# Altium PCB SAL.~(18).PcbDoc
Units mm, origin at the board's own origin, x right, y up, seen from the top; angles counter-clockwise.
Board outline 62 x 78 mm, 2 copper layers (Top Layer, Bottom Layer); 55 components, 64 nets, 231 pads, 15 vias.
Unrouted connection lines stored in the file: 1.
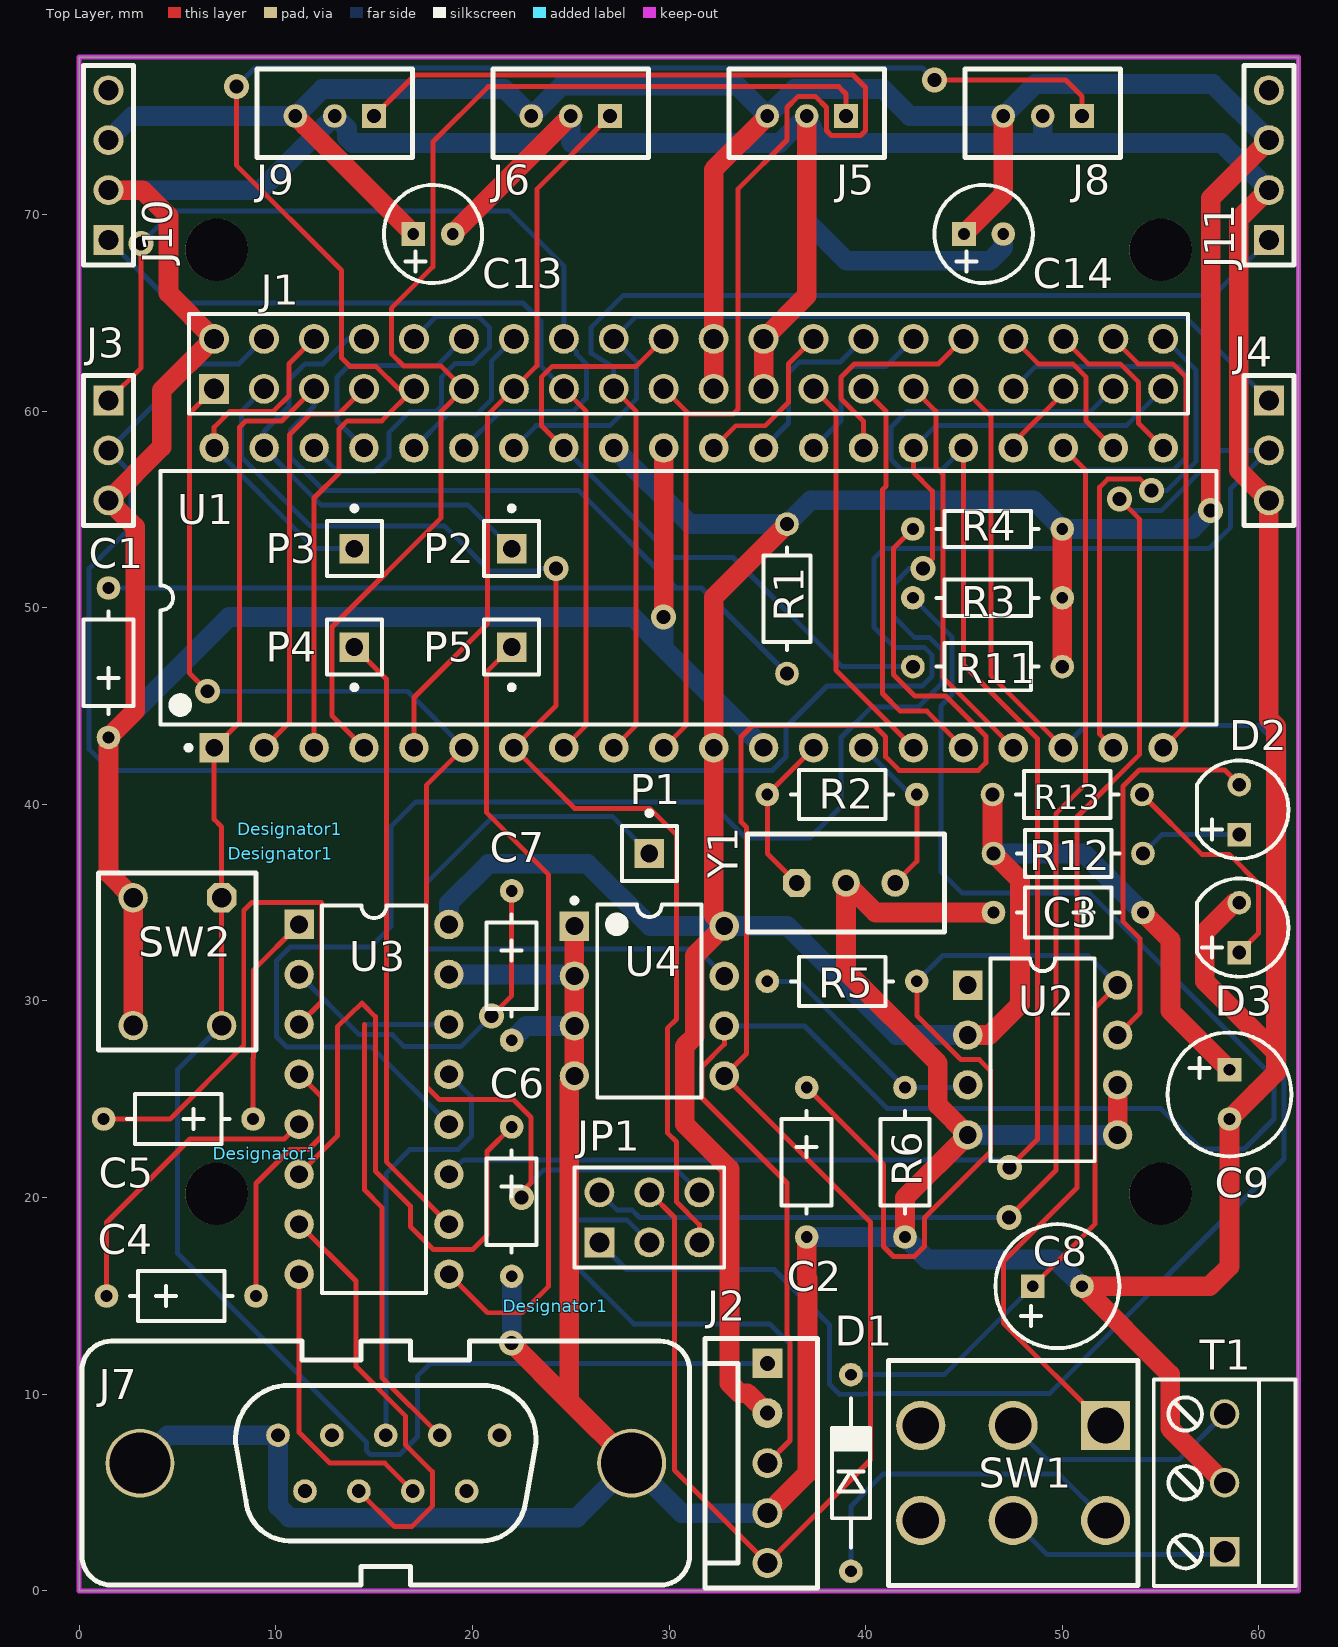
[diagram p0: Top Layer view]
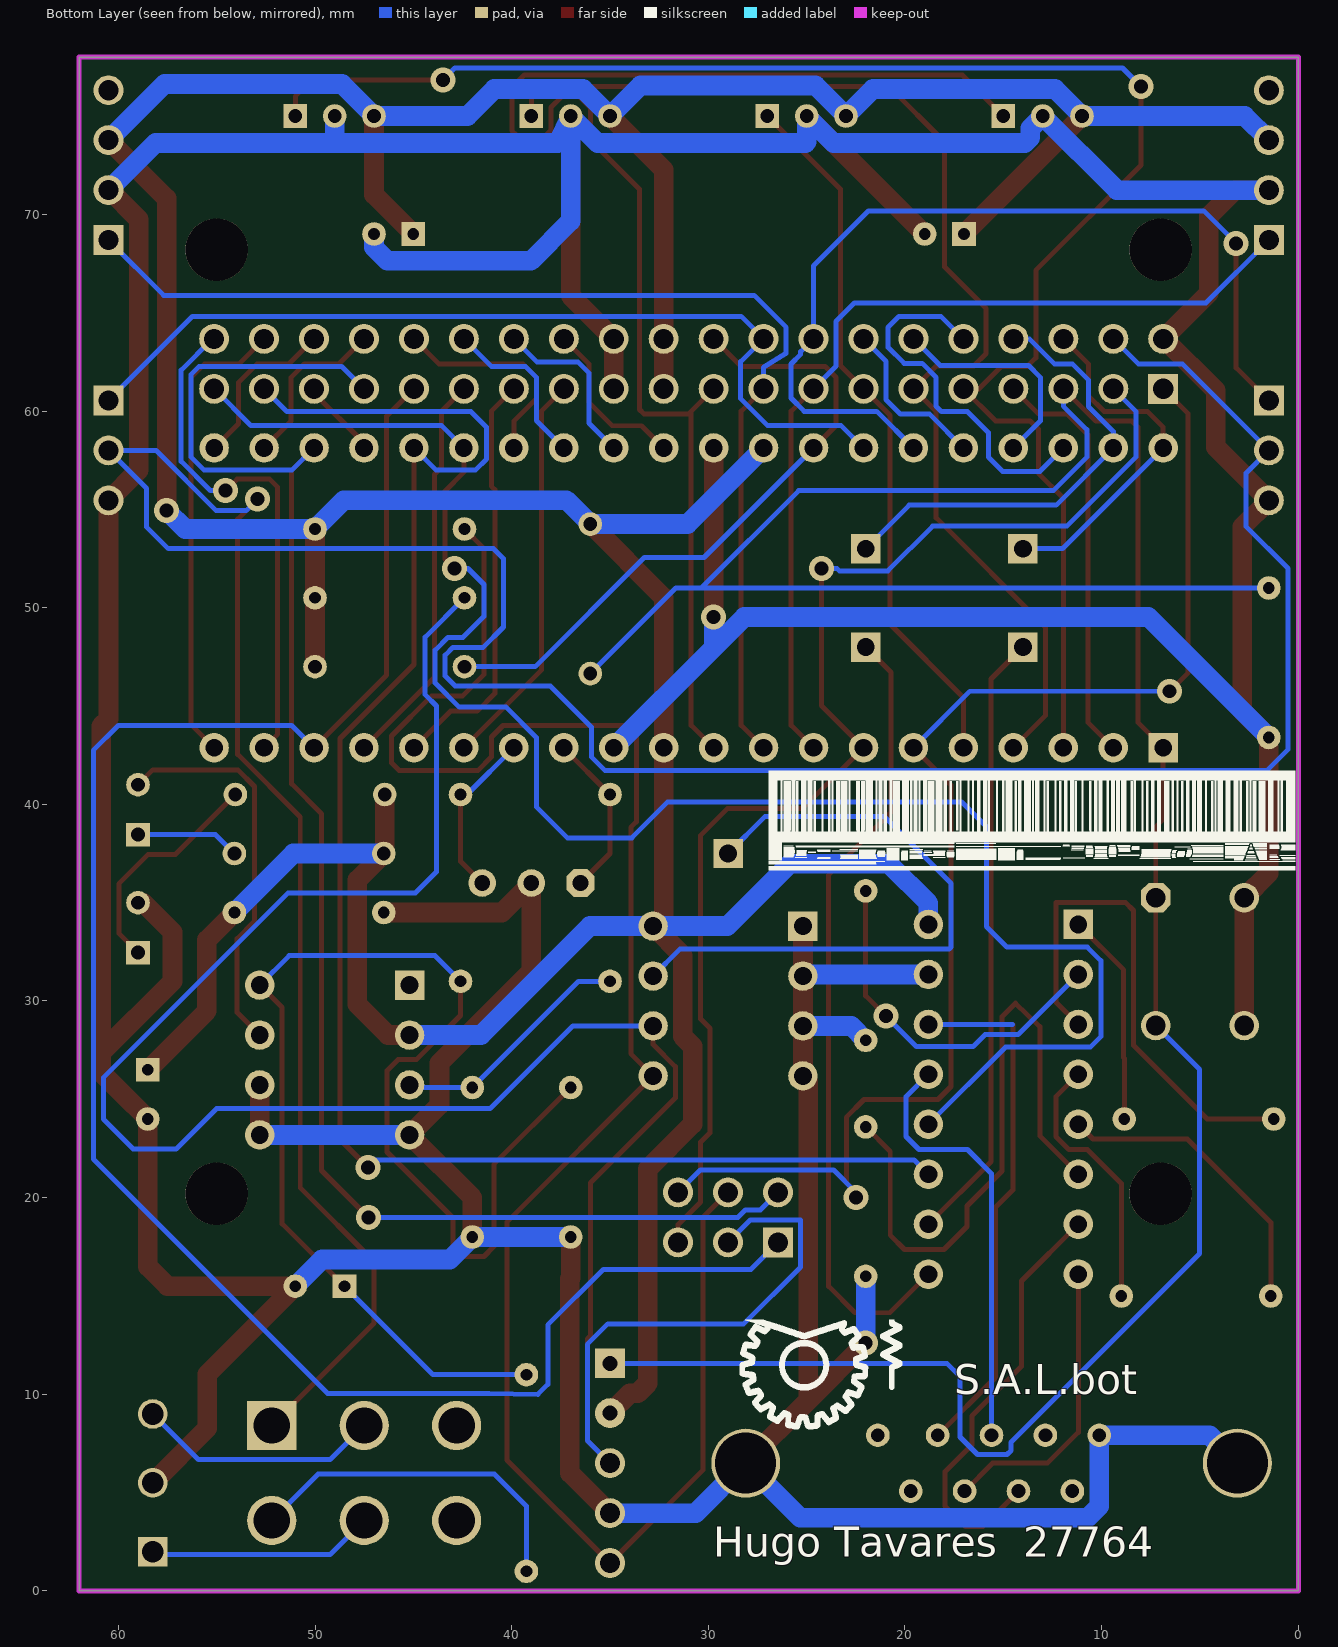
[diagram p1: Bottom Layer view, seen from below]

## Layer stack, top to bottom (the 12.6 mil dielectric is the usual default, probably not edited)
Top Layer: signal copper 0.0356
Dielectric: dielectric 0.32, FR-4, Dk 4.8
Bottom Layer: signal copper 0.0356

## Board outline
0,0 62,0 62,78 0,78

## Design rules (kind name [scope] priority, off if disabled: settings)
Clearance [All] p1: gap=0.25
PolygonConnect [All] p1: connectstyle=Relief reliefconductorwidth=0.254 reliefentries=4 polygonreliefangle="90 Angle"
RoomDefinition SAL [InComponentClass('SAL')] p1: confinementstyle=ConfineIn formatcopy=TRUE lockcomponents=FALSE outline 0,0 62,0 62,78 0,78
RoutingVias [All] p1: holewidth=0.711 width=1.27 viastyle="Through Hole" minholewidth=0.711 minwidth=1.27 maxholewidth=0.711 maxwidth=1.27
SilkscreenOverComponentPads [All] p1: minsilkscreentomaskgap=0.254
SolderMaskExpansion [All] p1: expansion=0.102
TestPointUsage [All] p1: valid=0 allowmultiple=FALSE
Testpoint [All] p1: side=15 testpointundercomponent=TRUE minsize=1.016 maxsize=2.54 preferedsize=1.524 minholesize=0 maxholesize=1.016 preferedholesize=0.813 testpointgrid=0.025 style=1023 order=0-112345678
Width Width_3 [InNet('VSS')] p1: maxlimit=1 minlimit=0.254 preferedwidth=1
Width Width_2 [InNet('VDD')] p2: maxlimit=1 minlimit=0.254 preferedwidth=1
Width Width_1 [All] p3: maxlimit=0.254 minlimit=0.254 preferedwidth=0.254
23 further rules are at their usual default settings.

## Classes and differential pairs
component class SAL: C1 C2 C3 C4 C5 C6 C7 C8 C9 C13 C14 D1 D2 D3 J1 J2 J3 J4 J5 J6 J7 J8 J9 J10 J11 JP1 P1 P2 P3 P4 P5 R1 R2 R3 R4 R5 R6 R11 R12 R13 SW1 SW2 T1 U1 U2 U3 U4 Y1

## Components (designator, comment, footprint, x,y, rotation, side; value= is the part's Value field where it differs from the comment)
C1 "0.1 uF" "KEMET C410C104M5U5CA-TR" 1.5,51 r270 top
C2 "0.1 uF" "KEMET C410C104M5U5CA-TR" 37,18 r90 top
C3 "0.1 uF" "KEMET C410C104M5U5CA-TR" 46.5,34.5 r0 top
C4 "0.1 uF" "KEMET C410C104M5U5CA-TR" 9,15 r180 top
C5 "0.1 uF" "KEMET C410C104M5U5CA-TR" 1.25,24 r0 top
C6 "0.1 uF" "KEMET C410C104M5U5CA-TR" 22,16 r90 top
C7 "0.1 uF" "KEMET C410C104M5U5CA-TR" 22,28 r90 top
C8 "100 uF" "PANASONIC ECA1CAK101X" 51,15.5 r180 top
C9 "100 uF" "PANASONIC ECA1CAK101X" 58.5,24 r90 top
C13 "33 uF" "PANASONIC ECEA0JKS330" 19,69 r180 top
C14 "33 uF" "PANASONIC ECEA0JKS330" 47,69 r180 top
D1 "FAIRCHILD 1N4148" "FAIRCHILD 1N4118" 39.25,1 r90 top
D2 "RED" "VISHAY TLLR4401" 59,41 r270 top
D3 "GREEN" "VISHAY TLLR4401" 59,35 r270 top
Designator1 "Klipper Graphic" untitled.bmp -16,16.25 r0 top
Designator1 "Klipper Graphic" untitled.bmp 9.5,22.25 r0 top
Designator1 "Klipper Graphic" untitled.bmp 10.25,37.5 r0 top
Designator1 "Klipper Graphic" untitled.bmp 24.25,14.5 r0 top
Designator1 "Klipper Graphic" untitled.bmp 10.75,38.75 r0 top
J1 "TSW-120-23-T-D" "SAMTEC TSW-120-XX-X-D" 31,62.4 r0 top
J2 "TYCO 640456-5" "TYCO 640456-5" 35,6.5 r90 top
J3 "TSW-100-23-T-S" "SAMTEC TSW-103-XX-X-S" 1.5,58 r270 top
J4 "TSW-100-23-T-S" "SAMTEC TSW-103-XX-X-S" 60.5,58 r270 top
J5 "PH Header" "JST B3B-PH-K-S(LF)(SN)" 37,75 r0 top
J6 "PH Header" "JST B3B-PH-K-S(LF)(SN)" 25,75 r0 top
J7 "DB9F Vertical" "TYCO 1-338313-2" 15.6,6.5 r0 top
J8 "PH Header" "JST B3B-PH-K-S(LF)(SN)" 49,75 r0 top
J9 "PH Header" "JST B3B-PH-K-S(LF)(SN)" 13,75 r0 top
J10 "TSW-104-07-G-S" "SAMTEC TSW-104-XX-X-S" 1.5,72.5 r90 top
J11 "TSW-104-07-G-S" "SAMTEC TSW-104-XX-X-S" 60.5,72.5 r90 top
JP1 "TSW-103-26-T-D" SAMTEC-103-XX-X-D 29,19 r0 top
P1 "Plug" PIN1 29,37.5 r0 top
P2 "CTS" PIN1 22,53 r0 top
P3 "RTS" PIN1 14,53 r0 top
P4 "RTS" PIN1 14,48 r180 top
P5 "CTS" PIN1 22,48 r180 top
R1 "1K" "TYCO 1-1625875-2" 36,46.65 r90 top
R2 "1M" "MULTICOMP MCF 0.25W 56R" 35,40.5 r0 top
R3 "4.7K" "MULTICOMP MF12 4K7" 42.4,50.5 r0 top
R4 "4.7K" "MULTICOMP MF12 4K7" 42.4,54 r0 top
R5 "7.5M" "VISHAY MRS25 2M4" 35,31 r0 top
R6 "2.4M" "VISHAY MRS25 2M4" 42,18 r90 top
R11 "1K" "TYCO 1-1625875-2" 42.4,47 r0 top
R12 "1K" "TYCO 1-1625875-2" 46.5,37.5 r0 top
R13 "1K" "TYCO 1-1625875-2" 54.05,40.5 r180 top
SW1 "C & K 1210M1S3CQE2" "C & K 1201M1S3CQE2" 47.5,6 r180 top
SW2 "OMRON B3F-1002" "OMRON B3F-1002" 5,32 r90 top
T1 "WIELAND ELECTRIC 25.195.0353.0" "WIELAND ELECTRIC 25.195.0353.0" 58.25,5.5 r90 top
U1 "PIC18F4620-I/P" PDIP600-P40 31,50.5 r90 top
U2 "MAX667CPA" JA8 49,27 r270 top
U3 "MAX232ACPE" PE16A 15,25 r270 top
U4 "24LC32A/P" PDIP300-P8 29,30 r0 top
Y1 "20.000 MHz" "AEL CRYSTALS C20M000000L01" 39,36 r0 top
? "" SAL_logo 25,11.5 r180 bottom
? "" Designed_logo 13.5,39 r180 bottom

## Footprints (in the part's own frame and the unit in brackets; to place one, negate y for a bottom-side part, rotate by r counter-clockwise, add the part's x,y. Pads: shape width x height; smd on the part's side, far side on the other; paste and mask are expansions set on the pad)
"AEL CRYSTALS C20M000000L01" [mm] "Resoator with caps"
  oct 1.4x1.4 hole 0.8: 1(-2.5,0)
  round 1.4 hole 0.8: 2(0,0) 3(2.5,0)
  silkscreen extent -5,-2.5 5,2.5
"C & K 1201M1S3CQE2" [mm] "DPDT Slide Switch"
  rect 2.5x2.5 hole 1.85: 1(-4.7,-2.415)
  round 2.5 hole 1.85: 2(0,-2.415) 3(4.7,-2.415) 4(-4.7,2.415) 5(0,2.415) 6(4.7,2.415)
  silkscreen extent -6.35,-5.71 6.35,5.72
Designed_logo [mm]
  silkscreen extent -13.45,-2.36 13.34,2.72
"FAIRCHILD 1N4118" [mm] "Diode"
  round 1.2 hole 0.6: A(0,0) K(10,0)
  silkscreen extent 1.2,-0.97 8.8,0.96
JA8 [mm] "DIP; 8 Leads; Row Spacing 7.62 mm; Pitch 2.54 mm"
  rect 1.5x1.5 hole 0.9: 1(-3.81,-3.81)
  round 1.5 hole 0.9: 2(-1.27,-3.81) 3(1.27,-3.81) 4(3.81,-3.81) 5(3.81,3.81) 6(1.27,3.81) 7(-1.27,3.81) 8(-3.81,3.81)
  silkscreen extent -5.15,-2.65 5.15,2.65
"JST B3B-PH-K-S(LF)(SN)" [mm] "2.0mm 3 pin Shrouded header"
  rect 1.2x1.2 hole 0.7: 1(2,0)
  round 1.2 hole 0.7: 2(0,0) 3(-2,0)
  silkscreen extent -3.95,-2.1 3.95,2.4
"KEMET C410C104M5U5CA-TR" [mm] "Axial Capacitor"
  round 1.2 hole 0.6: 1(0,0) 2(7.6,0)
  silkscreen extent 1.2,-1.27 6.4,1.27
"MULTICOMP MCF 0.25W 56R" [mm] "Axial Resistor"
  round 1.2 hole 0.6: 1(0,0) 2(7.6,0)
  silkscreen extent 1.2,-1.25 6.4,1.25
"MULTICOMP MF12 4K7" [mm] "Axial Resistor"
  round 1.2 hole 0.6: 1(0,0) 2(7.6,0)
  silkscreen extent 1.2,-0.92 6.4,0.93
"OMRON B3F-1002" [mm] "6.0mm Tactil Switch"
  oct 1.5x1.5 hole 1: 1(3.25,-2.25)
  round 1.5 hole 1: 2(-3.25,-2.25) 3(3.25,2.25) 4(-3.25,2.25)
  silkscreen extent -4.5,-4 4.5,4
"PANASONIC ECA1CAK101X" [mm] "Radial Capacitor"
  round 1.2 hole 0.6: 1(0,0)
  rect 1.2x1.2 hole 0.6: 2(2.5,0)
  silkscreen extent -1.9,-3.15 4.4,3.15
"PANASONIC ECEA0JKS330" [mm] "Radial Capacitor"
  round 1.2 hole 0.6: 1(0,0)
  rect 1.2x1.2 hole 0.6: 2(2,0)
  silkscreen extent -1.5,-2.5 3.5,2.5
PDIP300-P8 [mm] "DIP, 8-Leads, Row Spacing 7.62mm, Pitch 2.54mm, Body 9.5x6.6mm"
  rect 1.5x1.5 hole 0.9: 1(-3.81,3.81)
  round 1.5 hole 0.9: 2(-3.81,1.27) 3(-3.81,-1.27) 4(-3.81,-3.81) 5(3.81,-3.81) 6(3.81,-1.27) 7(3.81,1.27) 8(3.81,3.81)
  silkscreen extent -3.93,-4.9 2.65,5.23
PDIP600-P40 [mm] "DIP, 40-Leads, Row Spacing 15.24mm, Pitch 2.54mm, Body 51.8x13.5mm"
  rect 1.5x1.5 hole 0.9: 1(-7.62,24.13)
  round 1.5 hole 0.9: 2(-7.62,21.59) 3(-7.62,19.05) 4(-7.62,16.51) 5(-7.62,13.97) 6(-7.62,11.43) 7(-7.62,8.89) 8(-7.62,6.35) 9(-7.62,3.81) 10(-7.62,1.27) 11(-7.62,-1.27) 12(-7.62,-3.81) 13(-7.62,-6.35) 14(-7.62,-8.89) 15(-7.62,-11.43) 16(-7.62,-13.97) 17(-7.62,-16.51) 18(-7.62,-19.05) 19(-7.62,-21.59) 20(-7.62,-24.13) 21(7.62,-24.13) 22(7.62,-21.59) 23(7.62,-19.05) 24(7.62,-16.51) 25(7.62,-13.97) 26(7.62,-11.43) 27(7.62,-8.89) 28(7.62,-6.35) 29(7.62,-3.81) 30(7.62,-1.27) 31(7.62,1.27) 32(7.62,3.81) 33(7.62,6.35) 34(7.62,8.89) 35(7.62,11.43) 36(7.62,13.97) 37(7.62,16.51) 38(7.62,19.05) 39(7.62,21.59) 40(7.62,24.13)
  silkscreen extent -7.74,-26.85 6.45,26.85
PE16A [mm] "DIP; 16 Leads; Row Spacing 7.62 mm; Pitch 2.54 mm"
  rect 1.5x1.5 hole 0.9: 1(-8.89,-3.81)
  round 1.5 hole 0.9: 2(-6.35,-3.81) 3(-3.81,-3.81) 4(-1.27,-3.81) 5(1.27,-3.81) 6(3.81,-3.81) 7(6.35,-3.81) 8(8.89,-3.81) 9(8.89,3.81) 10(6.35,3.81) 11(3.81,3.81) 12(1.27,3.81) 13(-1.27,3.81) 14(-3.81,3.81) 15(-6.35,3.81) 16(-8.89,3.81)
  silkscreen extent -9.85,-2.65 9.85,2.65
PIN1 [mm] "Connector; Plug"
  rect 1.5x1.5 hole 0.9: 1(0,0)
  silkscreen extent -1.4,-1.4 1.4,2.17
SAL_logo [mm]
  silkscreen extent -4.6,-3.28 4.88,4.19
"SAMTEC TSW-103-XX-X-S" [mil] "3 pin 2.54mm pitch header"
  rect 60x60 hole 40.16: 1(-100,0)
  round 60 hole 40.16: 2(0,0) 3(100,0)
  silkscreen extent -150,-50 150,50
"SAMTEC TSW-104-XX-X-S" [mil] "4 pin 2.54mm pitch header"
  rect 60x60 hole 40.16: 1(-150,0)
  round 60 hole 40.16: 2(-50,0) 3(50,0) 4(150,0)
  silkscreen extent -200,-50 200,50
"SAMTEC TSW-120-XX-X-D" [mil] "40 pin 2.54mm pitch dual row header"
  rect 60x60 hole 40.16: 1(-950,-50)
  round 60 hole 40.16: 2(-950,50) 3(-850,-50) 4(-850,50) 5(-750,-50) 6(-750,50) 7(-650,-50) 8(-650,50) 9(-550,-50) 10(-550,50) 11(-450,-50) 12(-450,50) 13(-350,-50) 14(-350,50) 15(-250,-50) 16(-250,50) 17(-150,-50) 18(-150,50) 19(-50,-50) 20(-50,50) 21(50,-50) 22(50,50) 23(150,-50) 24(150,50) 25(250,-50) 26(250,50) 27(350,-50) 28(350,50) 29(450,-50) 30(450,50) 31(550,-50) 32(550,50) 33(650,-50) 34(650,50) 35(750,-50) 36(750,50) 37(850,-50) 38(850,50) 39(950,-50) 40(950,50)
  silkscreen extent -1000,-100 1000,100
SAMTEC-103-XX-X-D [mil] "6pin 2.54mm pitch dual row header"
  rect 60x60 hole 40.16: 1(-100,-50)
  round 60 hole 40.16: 2(-100,50) 3(0,-50) 4(0,50) 5(100,-50) 6(100,50)
  silkscreen extent -150,-100 150,100
"TYCO 1-338313-2" [mm] "DB9 Female PCB vertical mount"
  round 1.2 hole 0.7: 1(5.78,1.42) 2(2.74,1.42) 3(0,1.42) 4(-2.74,1.42) 5(-5.48,1.42) 6(4.11,-1.42) 7(1.37,-1.42) 8(-1.37,-1.42) 9(-4.11,-1.42)
  round 3.5 hole 3.1: 10(12.5,0) 11(-12.5,0)
  silkscreen extent -15.45,-6.2 15.45,6.2
"TYCO 1-1625875-2" [mm] "Axial Resistor"
  round 1.2 hole 0.7: 1(0,0) 2(7.6,0)
  silkscreen extent 1.2,-1.2 6.4,1.2
"TYCO 640456-5" [mil] "I2C Connector"
  rect 60x60 hole 30: 1(200,0)
  round 60 hole 30: 2(100,0)
  round 60 hole 40.16: 3(0,0) 4(-100,0) 5(-200,0)
  silkscreen extent -250,-100 250,125
untitled.bmp [mm]
"VISHAY MRS25 2M4" [mm] "Axial Resistor"
  round 1.2 hole 0.6: 1(0,0) 2(7.6,0)
  silkscreen extent 1.2,-1.25 6.4,1.25
"VISHAY TLLR4401" [mm] "3mm LED"
  round 1.2 hole 0.7: 1(0,0)
  rect 1.2x1.2 hole 0.7: 2(2.54,0)
  silkscreen extent -1.23,-2.17 3.77,2.5
"WIELAND ELECTRIC 25.195.0353.0" [mm] "3 position Terminal Block 3.5mm spacing"
  rect 1.5x1.5 hole 1.1: 1(-3.5,0)
  round 1.5 hole 1.1: 2(0,0) 3(3.5,0)
  silkscreen extent -5.25,-3.6 5.25,3.6

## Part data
C1 C2 C3 C4 C5 C6 C7: library part "KEMET C410C104M5U5CA-TR", "0.1 uF axial capacitor 50V Z5U"
C8 C9: library part "PANASONIC ECA1CAK101X", "100 uF radial aluminum electrolytic Capacitor 16V"
C13 C14: library part "PANASONIC ECEA0JKS330", "33 uF radial aluminium electrolytic Capacitor 6.3V"
D1: "Diode Switching 75V 500 MW DO-35"
D2: library part "VISHAY TLLR4401", "Red LED PCB 3mm"
D3: library part "VISHAY TLLG4401", "Green LED PCB 3mm"
Designator1 Designator1 Designator1 Designator1 Designator1: "Automatically created by Klipper"
J1: library part "SAMTEC TSW-120-07-G-D", "40 pin 2.54mm pitch dual row header"
J2: "I2C Connector"
J3 J4: library part "SAMTEC TSW-103-07-G-S", "3 pin 2.54mm pitch header"
J5 J6 J8 J9: library part "JST B3B-PH-K-S(LF)(SN)", "2.0mm 3-pin Shrouded header"
J7: library part "TYCO 1-338313-2", "DB9 Female PCB vertical mount"
J10 J11: library part "SAMTEC TSW-104-07-G-S", "4 pin 2.54mm pitch header"
JP1: library part "SAMTEC TSW-103-07-G-D", "6 pin 2.54mm pitch dual row header"
P2 P3 P4 P5: library part Plug, "Plug"
R1 R11 R12 R13: library part "TYCO 1-1625875-2", "1k Ohm 1/4 W 5%"
R2: library part "MULTICOMP MCF 0.25W 56R", "56 Ohm 1/4 W 5%"
R3 R4: library part "MULTICOMP MF12 4K7", "4.7k Ohm 1/4 W 5%"
R5 R6: library part "VISHAY MRS25 7M5", "7.5M Ohm 1/4 5%"
SW1: "DPDT Slide Switch"
SW2: "6.0mm Tact Switch"
T1: "3 position Terminal Block 3.5mm spacing"
U1: library part PIC16F877A-E/P, "Enhanced FLASH Microcontroller, 8K (x14-Bit words) FLASH, 368 Bytes RAM, 40-Pin PDIP, Standard VDD Range, Extended Temperature"
U2: library part MAX666MJA, "Dual Mode 5V/Programmable Micropower Voltage Regulator"
U3: "+5V Powered, Multi-Channel RS-232 Driver/Receiver"
U4: "32Kbit, 400kHz, 2.5V, I2C Serial EEPROM, 8-Pin PDIP, Commercial Temperature"
Y1: library part "AEL CRYSTALS C20M000000L01", "20.000 MHz Resoator with caps"

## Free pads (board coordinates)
  round 3.175 hole 3.175 unplated: 0(7,68.2) 1(55,68.2) 2(7,20.2) 3(55,20.2)

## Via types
v1: diameter 1.27, hole 0.711, Top Layer to Bottom Layer, 15 vias

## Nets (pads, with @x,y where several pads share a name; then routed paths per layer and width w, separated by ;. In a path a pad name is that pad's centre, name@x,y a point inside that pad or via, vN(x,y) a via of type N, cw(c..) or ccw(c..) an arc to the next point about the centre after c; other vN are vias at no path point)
232CTS: J7.7 U3.8 | length 15.1
  Top Layer w0.254: U3.8 11.19,8.066 12.76,6.496 15.554,6.496 J7.7
232RTS: J7.8 U3.7 | length 22.1
  Top Layer w0.254: U3.7 14.081,15.759 14.081,11.424 16.595,8.909 16.595,7.436 17.967,6.065 17.967,4.312 16.923,3.268 16.042,3.268 J7.8
232RX: J7.3 U3.13 | length 22.1
  Bottom Layer w0.254: J7.3 15.6,21.224 16.824,22.448 19.288,22.448 19.948,23.108 19.948,25.132 U3.13
232TX: J7.2 U3.14 | length 26.8
  Top Layer w0.254: 14.525,28.81 14.513,28.798 14.513,20.396 15.402,19.507 15.402,10.858 J7.2
  Bottom Layer w0.254: 14.525,28.81 U3.14
/INT: J1.20 R11.1 U1.33 | length 33.5
  Top Layer w0.254: U1.33 23.507,59.263 23.507,61.716 24.066,62.275 28.335,62.275 J1.20
  Bottom Layer w0.254: U1.33 30.223,52.547 33.258,52.547 38.804,47 R11.1
/RESET: C1.1 J1.5 J2.1 R1.1 SW2.1 SW2.2 U1.1 | length 150.4
  Top Layer w0.254: SW2.2 SW2.1 7.25,38.856 6.87,39.236 U1.1 8.163,44.173 8.163,59.176 8.466,59.479 10.299,59.479 J1.5
  Bottom Layer w0.254: C1.1 1.512,50.988 30.347,50.988 30.359,51 ; SW2.2 5.013,26.513 5.013,17.164 14.614,7.563 14.614,7.136 14.811,6.939 16.316,6.939 17.205,7.828 17.205,10.916 17.869,11.58 J2.1 ; J1.5 11.95,60.246 10.753,59.049 10.753,57.652 12.455,55.95 25.409,55.95 30.359,51 ; R1.1 31.65,51 ; 30.359,51 31.65,51 ; 30.359,51 31.65,51
A0: J1.7 U1.2 | length 21.2
  Top Layer w0.254: U1.2 10.703,44.173 10.703,58.795 11.744,59.836 13.196,59.836 J1.7
A4/LSDA: J1.1 JP1.6 U1.6 | length 69
  Top Layer w0.254: v1(6.545,45.75) 5.623,46.673 5.623,59.883 J1.1 ; U1.6 17.662,40.972 17.662,25.648 18.323,24.988 22.082,24.988 22.981,24.088 22.981,20.756 22.5,20.275 v1(22.5,20)
  Bottom Layer w0.254: v1(6.545,45.75) 16.7,45.75 U1.6 ; v1(22.5,20) 22.5,20.275 23.638,21.413 30.397,21.413 JP1.6
A5/LSCL: J1.3 JP1.5 U1.7 | length 64.1
  Top Layer w0.254: v1(24.25,52) 24.25,45.02 U1.7 25.194,39.796 29.016,39.796 30.388,38.424 30.388,29.083 29.917,28.612 29.917,23.297 30.388,22.826 30.388,19.781 31.54,18.628 JP1.5
  Bottom Layer w0.254: J1.3 8.264,59.984 8.264,57.652 11.769,54.147 18.591,54.147 20.869,51.869 23.336,51.869 23.467,52 v1(24.25,52)
B5: J1.10 U1.38 | length 19.2
  Bottom Layer w0.254: U1.38 13.134,56.936 15.041,56.936 15.757,57.652 15.757,58.897 16.824,59.963 18.145,59.963 18.424,60.243 18.424,61.716 19.129,62.421 20.043,62.421 20.863,63.24 20.863,64.256 20.304,64.815 18.175,64.815 J1.10
C0: J1.25 U1.15 | length 20.4
  Top Layer w0.254: J1.25 38.49,59.99 38.49,46.82 U1.15
C1: J1.27 U1.16 | length 21.3
  Top Layer w0.254: J1.27 41.03,59.99 41.03,56.176 40.854,56 40.854,45.634 41.753,44.736 43.114,44.736 U1.16
C2: J1.29 U1.17 | length 20.4
  Top Layer w0.254: J1.29 43.57,59.99 43.57,57.137 43.926,56.782 43.926,46.464 U1.17
C5: J1.35 U1.24 | length 4.1
  Top Layer w0.254: U1.24 47.51,58.37 50.05,60.91 J1.35
CTS: P5.1 U3.9 | length 40.8
  Top Layer w0.254: U3.9 20.772,14.148 22.545,14.148 23.885,15.488 23.885,36.418 20.71,39.593 20.71,46.71 P5.1
D0: J1.40 U1.19 | length 26.4
  Top Layer w0.254: U1.19 51.901,43.569 51.901,56.128 52.308,56.534 53.959,56.534 v1(54.543,55.95)
  Bottom Layer w0.254: v1(54.543,55.95) 55.312,55.95 56.804,57.442 56.804,62.079 55.212,63.67 J1.40
D1: J1.38 U1.20 | length 23.8
  Top Layer w0.254: J1.38 53.858,62.402 55.61,62.402 56.296,61.716 56.296,44.046 U1.20
D2: J1.36 U1.21 | length 8.6
  Top Layer w0.254: J1.36 51.318,62.402 52.94,62.402 53.883,61.46 53.883,59.367 U1.21
D3: J1.34 U1.22 | length 8.7
  Top Layer w0.254: J1.34 48.778,62.402 50.53,62.402 51.216,61.716 51.216,59.494 U1.22
D4: J1.32 U1.27 | length 11.1
  Top Layer w0.254: U1.27 39.89,59.481 38.744,60.627 38.744,61.716 39.43,62.402 43.702,62.402 J1.32
D5: J1.30 U1.28 | length 8.7
  Bottom Layer w0.254: U1.28 38.744,59.514 38.744,61.716 39.303,62.275 41.035,62.275 J1.30
D6: J1.28 U1.29 | length 8.9
  Bottom Layer w0.254: U1.29 36.077,59.387 36.077,61.945 36.636,62.503 38.723,62.503 J1.28
D7: J1.26 U1.30 | length 8.5
  Top Layer w0.254: U1.30 33.4,59.25 34.89,59.25 36.077,60.437 36.077,62.397 J1.26
EYEB: J1.19 J9.1 U1.10 | length 72.5
  Top Layer w0.254: J9.1 17.083,77.083 39.354,77.083 39.989,76.448 39.989,74.256 39.743,74.01 38.257,74.01 38.008,74.259 38.008,75.432 37.459,75.981 36.55,75.981 36.001,75.432 36.001,73.781 33.5,71.28 33.5,60.077 33.283,59.86 31,59.86 J1.19 ; U1.10 30.87,44.02 30.873,59.987
EYEF: J1.9 J8.1 U1.3 | length 86.7
  Top Layer w0.254: v1(8,76.5) 8,72.5 13.344,67.156 13.344,62.707 13.776,62.275 15.097,62.275 16.242,61.13 J1.9 15.4,59.5 13.643,59.5 13.217,59.074 13.217,56.839 11.95,55.572 U1.3 ; v1(43.5,76.829) 50.171,76.829 51,76 J8.1
  Bottom Layer w0.254: v1(8,76.5) 8.939,77.439 42.89,77.439 v1(43.5,76.829)
EYEL: J1.13 J6.1 U1.5 | length 36.2
  Top Layer w0.254: U1.5 17.03,45.435 20.761,49.166 20.761,59.781 J1.13 23.276,62.296 23.276,71.276 J6.1
EYER: J1.11 J5.1 U1.4 | length 61.2
  Top Layer w0.254: U1.4 12.862,44.508 12.862,49.016 18.413,54.567 18.413,59.973 J1.11 18.4,62.3 16.497,62.3 15.884,62.913 15.884,65.221 17.992,67.329 17.992,73.679 20.802,76.489 38.633,76.489 39,76.122 J5.1
JSCL: J2.3 JP1.3 R3.1 U4.6 | length 120.1
  Top Layer w0.254: U4.6 32.81,27.795 31.679,26.664 31.679,25.064 36.001,20.742 36.001,12.973 36.153,12.821 36.153,7.653 J2.3
  Bottom Layer w0.254: JP1.3 27.857,18.873 25.308,18.873 25.308,16.479 28.203,13.583 35.112,13.583 36.153,12.542 36.153,7.653 J2.3 ; U4.6 36.894,28.73 41.093,24.53 55,24.53 57.058,22.473 59.242,22.473 60.766,23.997 60.766,26.105 51.368,35.503 44.891,35.503 43.824,36.57 43.824,45.003 44.397,45.576 44.397,48.503 R3.1
JSDA: J2.5 JP1.4 R4.1 U4.5 | length 98.7
  Top Layer w0.254: JP1.4 30.277,18.993 30.277,6.143 J2.5 40.243,6.663 40.243,18.757 U4.5 33.944,27.324 33.944,38.831 33.664,39.11 33.664,43.428 34.248,44.012 40.437,44.012 41.021,43.428 41.021,42.412 41.707,41.726 45.729,41.726 46.11,42.107 46.11,43.479 44.088,45.501 42.512,45.501 41.419,46.594 41.419,53.019 R4.1
NetC2_2: C2.2 C8.2 D1.K R5.2 U2.8 | length 68.7
  Top Layer w0.254: C2.2 40.903,21.697 40.903,17.52 41.411,17.012 42.478,17.012 42.986,17.52 42.986,18.968 46.339,22.321 46.339,26.461 45.78,27.02 44.847,27.02 42.6,29.266 R5.2 ; C8.2 51.673,18.673 51.673,29.673 U2.8
  Bottom Layer w0.254: D1.K 44,11 C8.2 ; R5.2 43.903,32.303 51.317,32.303 U2.8
NetC4_1: C4.1 U3.4 | length 13.7
  Top Layer w0.254: C4.1 9,20.72 10.728,22.448 11.668,22.448 12.328,23.108 12.328,25.132 U3.4
NetC4_2: C4.2 U3.5 | length 15.6
  Top Layer w0.254: C4.2 1.4,18.733 5.648,22.981 10.441,22.981 U3.5
NetC5_1: C5.1 U3.3 | length 26.3
  Top Layer w0.254: C5.1 4.635,24 8.377,27.742 8.377,34.6 8.798,35.021 12.328,35.021 12.328,29.948 U3.3
NetC5_2: C5.2 U3.1 | length 10.9
  Top Layer w0.254: C5.2 8.85,27.088 8.881,27.119 8.881,31.581 U3.1
NetC6_2: C6.2 U3.6 | length 33.1
  Top Layer w0.254: U3.6 13.141,23.141 13.141,28.696 14.386,29.89 15.071,29.204 15.071,21.355 16.849,19.577 16.849,18.536 18.018,17.368 20.024,17.368 20.75,18.093 20.75,22.35 C6.2
NetC7_2: C7.2 U3.2 | length 18.7
  Top Layer w0.254: v1(20.964,29.229) 22,30.265 C7.2
  Bottom Layer w0.254: U3.2 14.25,28.29 15.935,28.29 16.545,27.68 19.415,27.68 v1(20.964,29.229)
NetD1_A: D1.A SW1.4 | length 17.9
  Bottom Layer w0.254: D1.A 39.25,4.312 40.876,5.938 49.847,5.938 SW1.4
NetD2_1: D2.1 U2.7 | length 20.1
  Top Layer w0.254: U2.7 53.959,29.419 53.959,33.166 53.073,34.052 53.073,40.905 53.92,41.752 58.248,41.752 D2.1
NetD2_2: D2.2 R12.2 | length 5.3
  Bottom Layer w0.254: R12.2 55.06,38.46 D2.2
NetD3_2: D3.2 R13.1 | length 11.7
  Top Layer w0.254: R13.1 57.091,37.459 58.48,37.459 59.978,35.961 59.978,33.439 D3.2
NetP1_1: P1.1 U4.7 | length 32.5
  Bottom Layer w0.254: P1.1 27.111,39.389 21.066,39.389 17.662,35.986 17.662,32.735 17.764,32.633 31.447,32.633 U4.7
NetR5_1: R5.1 R6.2 U2.3 | length 12.5
  Bottom Layer w0.254: R5.1 36.6,31 R6.2 45.06,25.6 U2.3
NetSW1_2: SW1.2 T1.3 | length 12.4
  Bottom Layer w0.254: SW1.2 49.241,6.674 55.924,6.674 T1.3
NetSW1_5: SW1.5 T1.1 | length 11.5
  Bottom Layer w0.254: SW1.5 49.237,1.848 58.098,1.848 T1.1
PWM1/SERVOR: J1.18 J4.1 U1.34 | length 46.4
  Bottom Layer w0.254: U1.34 23.243,59.253 26.985,59.253 28.356,60.624 28.356,62.504 J1.18 28.333,64.813 56.227,64.813 J4.1
PWM2/SERVOL: J1.16 J3.1 U1.35 | length 46.5
  Top Layer w0.254: J3.1 3.159,62.199 v1(3.159,68.523)
  Bottom Layer w0.254: v1(3.159,68.523) 4.81,70.174 21.856,70.174 24.65,67.38 J1.16 25.305,63.015 25.305,62.878 25.793,62.389 25.793,60.657 25.123,59.987 21.437,59.987 U1.35
PWM3: J1.14 U1.36 | length 8.5
  Bottom Layer w0.254: U1.36 18.746,59.836 20.228,59.836 20.964,60.573 20.964,62.524 J1.14
PWM4: J1.12 U1.37 | length 11.4
  Bottom Layer w0.254: U1.37 13.116,59.494 13.116,61.716 13.715,62.316 18.216,62.316 J1.12
RTS: P4.1 U3.10 | length 31.3
  Top Layer w0.254: P4.1 15.63,46.37 15.63,21.83 U3.10
RX: J1.39 U1.26 U3.12 | length 89.7
  Top Layer w0.254: U1.26 42.43,56.887 43.392,55.925 43.392,52.47 v1(42.91,51.988)
  Bottom Layer w0.254: U3.12 14.885,27.655 10.576,27.655 10.042,28.188 10.042,32.049 10.728,32.735 14.817,32.735 15.859,33.776 15.859,38.856 17.129,40.126 32.064,40.126 33.893,38.297 37.169,38.297 38.744,39.872 38.744,43.403 40.282,44.94 42.662,44.94 43.889,46.168 43.889,47.84 43.24,48.489 42.478,48.489 41.411,49.556 41.411,51.175 42.224,51.988 v1(42.91,51.988) ; U1.26 43.562,59.252 53.252,59.252 J1.39
SCL: J1.31 JP1.1 U1.18 | length 98.1
  Top Layer w0.254: J1.31 46.364,59.736 46.364,46.566 U1.18
  Bottom Layer w0.254: JP1.1 27.838,16.352 35.341,16.352 38.16,13.532 38.16,10.51 38.668,10.002 41.157,10.052 49.361,10.052 61.274,21.965 61.274,42.742 60.004,44.012 51.182,44.012 U1.18
SDA: J1.33 JP1.2 U1.23 | length 83.2
  Top Layer w0.254: v1(47.282,18.993) 49.666,21.377 49.666,39.516 51.19,41.04 51.19,56.98 U1.23
  Bottom Layer w0.254: JP1.2 27.349,19.381 28.111,19.381 28.499,18.993 v1(47.282,18.993) ; J1.33 48.653,62.273 55.891,62.273 56.296,61.868 56.296,57.652 55.633,56.989 51.181,56.989 U1.23
TX: J1.37 U1.25 U3.11 | length 85.8
  Top Layer w0.254: U1.25 44.97,47.108 48.727,43.351 48.727,22.955 v1(47.305,21.533)
  Bottom Layer w0.254: U3.11 19.541,21.921 46.917,21.921 v1(47.305,21.533) ; U1.25 43.839,56.989 41.846,56.989 41.284,57.55 41.284,59.176 42.072,59.963 51.423,59.963 J1.37
US_B: J1.17 J11.1 U1.9 | length 59.3
  Top Layer w0.254: U1.9 28.33,44.02 28.33,59.99 J1.17
  Bottom Layer w0.254: J1.17 27.19,62.224 26.044,62.935 26.044,64.256 27.67,65.882 57.692,65.882 J11.1
US_B_RX: J11.4
US_F: J1.15 J10.1 U1.8 | length 46.8
  Top Layer w0.254: U1.8 25.79,44.02 25.79,59.99 J1.15
  Bottom Layer w0.254: J10.1 4.702,65.488 22.577,65.488 23.504,64.561 23.504,62.276 J1.15
US_F_RX: J10.4
V+: J1.4 J3.2 J4.2 SW1.1 | length 166.3
  Top Layer w0.254: SW1.1 47,13.615 47,16.75 50.75,20.5 50.75,39.356 53.933,42.539 53.933,54.502 v1(52.917,55.518)
  Bottom Layer w0.254: J1.4 8.137,62.397 5.897,62.397 J3.2 2.651,56.849 2.651,54.121 0.517,51.988 0.517,42.793 1.584,41.726 35.264,41.726 35.95,42.412 35.95,43.936 38.033,46.019 42.873,46.019 43.381,46.527 43.381,47.586 42.986,47.981 41.449,47.981 40.414,49.016 40.414,52.489 40.925,53 57.46,53 58.556,54.096 58.556,56.056 J4.2 58.088,58 55.022,54.934 53.502,54.934 v1(52.917,55.518)
VDD: C3.2 C9.2 C13.2 C14.2 J1.21 J1.22 J2.2 J5.3 J6.3 J8.3 J9.3 J10.3 J11.3 R1.2 R3.2 R4.2 R11.2 R12.1 R13.2 U1.11 U1.32 U2.2 U3.16 U4.8 | length 270.7
  Top Layer w1: J9.3 11.49,74.51 C13.2 ; J1.21 J1.22 32.27,72.27 J5.3 ; J2.2 33.984,10.056 33.588,10.056 33.08,10.564 33.08,21.457 30.798,23.739 30.798,27.698 31.302,28.202 31.302,32.302 U4.8 32.27,34.35 U1.11 32.27,50.52 R1.2 ; C14.2 47,71 J8.3 ; U2.2 46.288,28.27 47.85,29.832 47.85,36.15 R12.1 46.45,37.55 R13.2 ; R11.2 R3.2 R4.2 ; C3.2 55.5,33.1 55.5,29.5 C9.2 ; v1(57.54,54.944) 57.54,70.81 J11.3
  Bottom Layer w1: J10.3 2.73,75 J9.3 12.372,76.372 21.628,76.372 J6.3 24.55,76.55 33.45,76.55 J5.3 36.372,76.372 40.878,76.372 42.25,75 J8.3 48.626,76.626 57.644,76.626 J11.3 ; U3.16 18.81,34.975 20.812,36.976 25.866,36.976 29.033,33.81 U4.8 36.018,33.81 41.558,28.27 U2.2 ; U1.32 31.06,54.25 R1.2 37.218,55.468 48.532,55.468 R4.2 56.596,54 v1(57.54,54.944) ; R12.1 51.1,37.5 C3.2
VSS: C1.2 C2.1 C3.1 C6.1 C7.1 C8.1 C9.1 C13.1 C14.1 D3.1 J1.2 J1.23 J1.24 J2.4 J3.3 J4.3 J5.2 J6.2 J7.5 J7.10 J7.11 J8.2 J9.2 J10.2 J11.2 R6.1 SW2.3 SW2.4 T1.2 U1.12 U1.31 U2.4 U2.5 U2.6 U3.15 U4.1 U4.2 U4.3 U4.4 Y1.2 | length 473.9
  Top Layer w1: J10.2 3.23,71.23 4.548,69.912 4.548,65.992 J1.2 6.825,63.67 4.2,61.045 4.2,58.16 J3.3 2.854,54.106 2.854,44.754 C1.2 1.5,36.5 SW2.3 SW2.4 ; C13.1 J6.2 ; v1(22,12.6) 24.927,9.673 ; U4.1 U4.2 U4.3 U4.4 24.927,25.927 24.927,9.673 ; v1(29.73,49.524) U1.31 ; J1.23 J1.24 37,65.86 J5.2 ; J2.4 37.042,6.002 37.042,15.869 37,15.911 C2.1 ; R6.1 42,20 U2.4 43.672,24.708 43.672,26.842 39,31.514 Y1.2 40.5,34.5 C3.1 ; U2.5 U2.6 ; T1.2 55.483,8.267 55.483,11.017 C8.1 57.496,15.5 58.5,16.504 C9.1 ; D3.1 58.75,35 57.25,33.5 57.25,31 60.868,27.382 60.868,26.368 ; J11.2 60.455,71.23 58.963,69.737 58.963,56.997 J4.3 60.5,44.342 60.868,43.975 60.868,26.368 ; 24.927,9.673 J7.10 24.927,9.673 ; C9.1 60.868,26.368 ; C9.1 59.852,25.352 60.868,26.368
  Bottom Layer w1: C1.2 7.624,49.524 28.166,49.524 29.73,47.96 ; J10.2 9.23,71.23 J9.2 13.624,74.376 13.624,73.908 13.903,73.629 23.629,73.629 J6.2 25,73.685 25.056,73.629 35.629,73.629 J5.2 ; J7.11 4.52,7.92 J7.5 10.12,4.312 10.704,3.728 25.328,3.728 J7.10 30.64,3.96 J2.4 ; U3.15 25.11,31.35 U4.2 ; v1(22,12.6) C6.1 ; C7.1 22.73,28.73 U4.3 ; v1(29.73,49.524) 29.73,47.96 ; C2.1 R6.1 43.14,16.86 49.64,16.86 C8.1 ; U2.4 U2.5 ; C14.1 47,68.32 46.314,67.634 39.024,67.634 37,69.658 J5.2 ; J8.2 49,73.629 ; J11.2 58.101,73.629 ; 29.73,47.96 U1.12 29.73,47.96 ; J5.2 37.652,73.629 49,73.629 ; 49,73.629 58.101,73.629 ; 49,73.629 58.101,73.629
XAXIS: J1.8 P2.1 U1.39 | length 23.4
  Bottom Layer w0.254: J1.8 13.674,63.67 12.406,62.402 11.49,62.402 10.676,61.587 10.676,60.227 9.41,58.961 U1.39 12.316,55.214 19.786,55.214 P2.1
XIN: R2.1 U1.13 Y1.1 | length 8.5
  Top Layer w0.254: Y1.1 35,37.5 R2.1 37.35,42.85 U1.13
XOUT: R2.2 U1.14 Y1.3 | length 8.7
  Top Layer w0.254: Y1.3 42.6,37.1 R2.2
  Bottom Layer w0.254: U1.14 42.27,40.5 R2.2
YAXIS: J1.6 P3.1 U1.40 | length 18.2
  Top Layer w0.254: U1.40 6.87,59.177 7.68,59.987 9.883,59.987 10.677,60.781 10.677,62.397 J1.6
  Bottom Layer w0.254: U1.40 11.99,53 P3.1
pads on no net: J7.1 J7.4 J7.6 J7.9 SW1.3 SW1.6 U2.1

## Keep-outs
Keep-Out Layer:
  the board outline again, w0.254

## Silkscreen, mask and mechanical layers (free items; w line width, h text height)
Bottom Overlay:
  text "S.A.L.bot" at 17.5,10 h1.52
  text "Hugo Tavares  27764" at 29.75,1.75 h1.52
